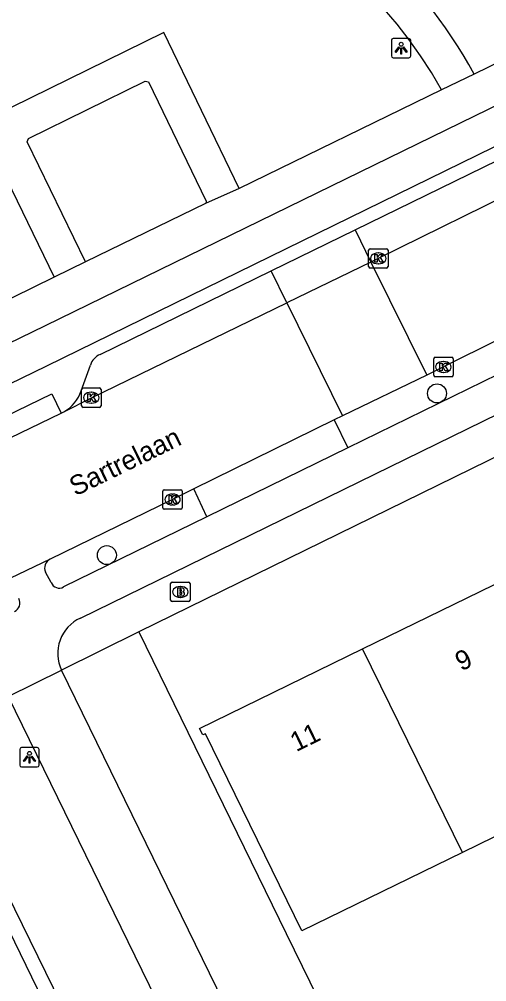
# Model space of a CAD drawing. Extents: x 160457 to 162082, y 388340 to 389736.
# Drawn here: x 160818.95 to 160843.03, y 388835.85 to 388885.46 of the extents above; entities that cross this region are included whole.
import ezdxf

# ---------------------------------------------------------------- set-up
doc = ezdxf.new("R2010")
doc.units = 0
for name, color, linetype in [('IMGEO_Berm_groen', 7, 'Continuous'), ('IMGEO_Boom', 7, 'Continuous'), ('IMGEO_Brandkraan', 7, 'Continuous'), ('IMGEO_Fietspad_gesloten', 7, 'Continuous'), ('IMGEO_Fietspad_open', 7, 'Continuous'), ('IMGEO_Kolk', 7, 'Continuous'), ('IMGEO_Lichtpunt', 7, 'Continuous'), ('IMGEO_Openbare_ruimte_label', 7, 'Continuous'), ('IMGEO_Pand', 7, 'Continuous'), ('IMGEO_Pand_nummerreeks', 7, 'Continuous'), ('IMGEO_Parkeervlak_open', 7, 'Continuous'), ('IMGEO_Rijbaan_lokaal_gesloten', 7, 'Continuous'), ('IMGEO_Rijbaan_lokaal_open', 7, 'Continuous'), ('IMGEO_Verkeerseiland_open', 7, 'Continuous'), ('IMGEO_Voetpad_open', 7, 'Continuous')]:
    doc.layers.add(name, color=color, linetype=linetype)

msp = doc.modelspace()

# ---------------------------------------------------------------- linework, layer by layer
at = {"layer": 'IMGEO_Berm_groen'}
for points in [[(160825.107, 388853.891), (160832.7, 388838.342), (160837.199, 388829.157)], [(160826.4, 388823.92), (160821.923, 388833.073), (160814.32, 388848.575)]]:
    msp.add_lwpolyline(points, dxfattribs=at)
at = {"layer": 'IMGEO_Boom'}
for centre in [(160840.468, 388866.179), (160823.466, 388857.844)]:
    msp.add_circle(centre, 0.489, dxfattribs=at)
at = {"layer": 'IMGEO_Brandkraan'}
for p, q in [((160826.75, 388855.52), (160826.75, 388856.372)), ((160826.825, 388856.446), (160827.677, 388856.446)), ((160827.238, 388856.226), (160827.263, 388856.226)), ((160827.751, 388856.372), (160827.751, 388855.52)), ((160827.677, 388855.446), (160826.825, 388855.446)), ((160827.261, 388855.666), (160827.236, 388855.666))]:
    msp.add_line(p, q, dxfattribs=at)
for points in [[(160826.75, 388855.52), (160826.75, 388856.372)], [(160826.825, 388856.446), (160827.677, 388856.446)], [(160827.751, 388856.372), (160827.751, 388855.52)], [(160827.098, 388856.146), (160827.098, 388855.746), (160827.311, 388855.746)], [(160827.329, 388856.146), (160827.098, 388856.146)], [(160827.277, 388856.065), (160827.223, 388856.065), (160827.223, 388855.989)], [(160827.223, 388855.989), (160827.276, 388855.989)], [(160827.285, 388855.913), (160827.223, 388855.913), (160827.223, 388855.832)], [(160827.223, 388855.832), (160827.285, 388855.832)], [(160827.677, 388855.446), (160826.825, 388855.446)]]:
    msp.add_lwpolyline(points, dxfattribs=at)
for centre, radius, start, end in [((160826.827, 388856.37), 0.0765, 91.552, 178.448), ((160826.827, 388856.37), 0.0765, 91.552, 178.448), ((160827.675, 388856.37), 0.0765, 1.552, 88.448), ((160827.675, 388856.37), 0.0765, 1.552, 88.448), ((160827.278, 388856.027), 0.0379, 267.8285, 90.9355), ((160827.286, 388855.872), 0.0404, 269.8759, 90.5077), ((160827.317, 388855.997), 0.251, 268.6676, 293.5347), ((160827.333, 388856.001), 0.145, 59.4692, 91.5367), ((160827.358, 388856.048), 0.0922, 285.5137, 58.1501), ((160827.363, 388855.856), 0.105, 301.3115, 78.989), ((160826.827, 388855.522), 0.0765, 181.552, 268.448), ((160826.827, 388855.522), 0.0765, 181.552, 268.448), ((160827.675, 388855.522), 0.0765, 271.552, 358.448), ((160827.675, 388855.522), 0.0765, 271.552, 358.448)]:
    msp.add_arc(centre, radius, start, end, dxfattribs=at)
for centre, major_axis, ratio, start_param, end_param in [((160827.237, 388855.946), (-0.387, 0.002), 0.722429, 4.712389, 7.853982), ((160827.262, 388855.946), (-0.39, 0.002), 0.717154, 1.570796, 4.712389)]:
    msp.add_ellipse(centre, major_axis=major_axis, ratio=ratio, start_param=start_param, end_param=end_param, dxfattribs=at)
at = {"layer": 'IMGEO_Fietspad_gesloten'}
for points in [[(160812.524, 388865.895), (160820.314, 388869.678), (160924.149, 388920.448), (160929.542, 388923.081)], [(160909.887, 388911.468), (160820.353, 388867.581), (160804.958, 388860.084), (160761.388, 388838.743), (160740.999, 388828.766), (160723.804, 388820.325)]]:
    msp.add_lwpolyline(points, dxfattribs=at)
at = {"layer": 'IMGEO_Fietspad_open'}
for points in [[(160822.105, 388854.6), (160868.356, 388877.242), (160931.655, 388908.25)], [(160844.374, 388867.53), (160835.881, 388863.365)], [(160835.881, 388863.365), (160828.618, 388859.824)], [(160828.618, 388859.824), (160821.23, 388856.204)], [(160820.601, 388856.424), (160820.3, 388856.966)]]:
    msp.add_lwpolyline(points, dxfattribs=at)
for centre, radius, start, end in [((160820.788, 388857.172), 0.529, 118.04, 202.8574), ((160821.008, 388856.579), 0.436, 200.8773, 300.567), ((160818.502, 388855.371), 0.485, 295.3905, 28.3574), ((160822.935, 388852.782), 1.999, 114.5332, 205.9112)]:
    msp.add_arc(centre, radius, start, end, dxfattribs=at)
at = {"layer": 'IMGEO_Kolk'}
for p, q in [((160837.019, 388873.637), (160837.871, 388873.637)), ((160836.944, 388872.711), (160836.944, 388873.563)), ((160837.432, 388873.417), (160837.457, 388873.417)), ((160837.945, 388873.563), (160837.945, 388872.711)), ((160837.871, 388872.637), (160837.019, 388872.637)), ((160837.455, 388872.857), (160837.43, 388872.857)), ((160840.296, 388867.114), (160840.296, 388867.966)), ((160840.371, 388868.04), (160841.223, 388868.04)), ((160840.784, 388867.82), (160840.809, 388867.82)), ((160841.297, 388867.966), (160841.297, 388867.114)), ((160840.807, 388867.26), (160840.782, 388867.26)), ((160841.223, 388867.04), (160840.371, 388867.04)), ((160822.165, 388865.531), (160822.165, 388866.383)), ((160822.24, 388866.457), (160823.092, 388866.457)), ((160822.653, 388866.237), (160822.678, 388866.237)), ((160823.166, 388866.383), (160823.166, 388865.531)), ((160822.676, 388865.677), (160822.651, 388865.677)), ((160823.092, 388865.457), (160822.24, 388865.457)), ((160826.422, 388861.21), (160827.274, 388861.21)), ((160826.347, 388860.284), (160826.347, 388861.136)), ((160826.835, 388860.99), (160826.86, 388860.99)), ((160827.348, 388861.136), (160827.348, 388860.284)), ((160827.274, 388860.21), (160826.422, 388860.21)), ((160826.858, 388860.43), (160826.833, 388860.43))]:
    msp.add_line(p, q, dxfattribs=at)
for points in [[(160837.019, 388873.637), (160837.871, 388873.637)], [(160836.944, 388872.711), (160836.944, 388873.563)], [(160837.265, 388873.337), (160837.388, 388873.337), (160837.388, 388873.186), (160837.518, 388873.337), (160837.682, 388873.337), (160837.536, 388873.186), (160837.689, 388872.937), (160837.537, 388872.937), (160837.452, 388873.101), (160837.388, 388873.034), (160837.388, 388872.937), (160837.265, 388872.937), (160837.265, 388873.337)], [(160837.945, 388873.563), (160837.945, 388872.711)], [(160837.871, 388872.637), (160837.019, 388872.637)], [(160840.296, 388867.114), (160840.296, 388867.966)], [(160840.371, 388868.04), (160841.223, 388868.04)], [(160840.617, 388867.74), (160840.74, 388867.74), (160840.74, 388867.589), (160840.87, 388867.74), (160841.034, 388867.74), (160840.888, 388867.589), (160841.041, 388867.34), (160840.889, 388867.34), (160840.804, 388867.504), (160840.74, 388867.437), (160840.74, 388867.34), (160840.617, 388867.34), (160840.617, 388867.74)], [(160841.297, 388867.966), (160841.297, 388867.114)], [(160841.223, 388867.04), (160840.371, 388867.04)], [(160822.165, 388865.531), (160822.165, 388866.383)], [(160822.24, 388866.457), (160823.092, 388866.457)], [(160822.486, 388866.157), (160822.609, 388866.157), (160822.609, 388866.006), (160822.739, 388866.157), (160822.903, 388866.157), (160822.757, 388866.006), (160822.91, 388865.757), (160822.758, 388865.757), (160822.673, 388865.921), (160822.609, 388865.854), (160822.609, 388865.757), (160822.486, 388865.757), (160822.486, 388866.157)], [(160823.166, 388866.383), (160823.166, 388865.531)], [(160823.092, 388865.457), (160822.24, 388865.457)], [(160826.422, 388861.21), (160827.274, 388861.21)], [(160826.347, 388860.284), (160826.347, 388861.136)], [(160826.668, 388860.91), (160826.791, 388860.91), (160826.791, 388860.759), (160826.921, 388860.91), (160827.085, 388860.91), (160826.939, 388860.759), (160827.092, 388860.51), (160826.94, 388860.51), (160826.855, 388860.674), (160826.791, 388860.607), (160826.791, 388860.51), (160826.668, 388860.51), (160826.668, 388860.91)], [(160827.348, 388861.136), (160827.348, 388860.284)], [(160827.274, 388860.21), (160826.422, 388860.21)]]:
    msp.add_lwpolyline(points, dxfattribs=at)
for centre, start, end in [((160837.021, 388873.561), 91.552, 178.448), ((160837.021, 388873.561), 91.552, 178.448), ((160837.869, 388873.561), 1.552, 88.448), ((160837.869, 388873.561), 1.552, 88.448), ((160837.021, 388872.713), 181.552, 268.448), ((160837.021, 388872.713), 181.552, 268.448), ((160837.869, 388872.713), 271.552, 358.448), ((160837.869, 388872.713), 271.552, 358.448), ((160840.373, 388867.964), 91.552, 178.448), ((160840.373, 388867.964), 91.552, 178.448), ((160841.221, 388867.964), 1.552, 88.448), ((160841.221, 388867.964), 1.552, 88.448), ((160840.373, 388867.116), 181.552, 268.448), ((160840.373, 388867.116), 181.552, 268.448), ((160841.221, 388867.116), 271.552, 358.448), ((160841.221, 388867.116), 271.552, 358.448), ((160822.242, 388866.381), 91.552, 178.448), ((160822.242, 388866.381), 91.552, 178.448), ((160823.09, 388866.381), 1.552, 88.448), ((160823.09, 388866.381), 1.552, 88.448), ((160822.242, 388865.533), 181.552, 268.448), ((160822.242, 388865.533), 181.552, 268.448), ((160823.09, 388865.533), 271.552, 358.448), ((160823.09, 388865.533), 271.552, 358.448), ((160826.424, 388861.134), 91.552, 178.448), ((160826.424, 388861.134), 91.552, 178.448), ((160827.272, 388861.134), 1.552, 88.448), ((160827.272, 388861.134), 1.552, 88.448), ((160826.424, 388860.286), 181.552, 268.448), ((160826.424, 388860.286), 181.552, 268.448), ((160827.272, 388860.286), 271.552, 358.448), ((160827.272, 388860.286), 271.552, 358.448)]:
    msp.add_arc(centre, 0.0765, start, end, dxfattribs=at)
for centre, major_axis, ratio, start_param, end_param in [((160837.431, 388873.137), (-0.387, 0.002), 0.722429, 4.712389, 7.853982), ((160837.456, 388873.137), (-0.39, 0.002), 0.717154, 1.570796, 4.712389), ((160840.783, 388867.54), (-0.387, 0.002), 0.722429, 4.712389, 7.853982), ((160840.808, 388867.54), (-0.39, 0.002), 0.717154, 1.570796, 4.712389), ((160822.652, 388865.957), (-0.387, 0.002), 0.722429, 4.712389, 7.853982), ((160822.677, 388865.957), (-0.39, 0.002), 0.717154, 1.570796, 4.712389), ((160826.834, 388860.71), (-0.387, 0.002), 0.722429, 4.712389, 7.853982), ((160826.859, 388860.71), (-0.39, 0.002), 0.717154, 1.570796, 4.712389)]:
    msp.add_ellipse(centre, major_axis=major_axis, ratio=ratio, start_param=start_param, end_param=end_param, dxfattribs=at)
at = {"layer": 'IMGEO_Lichtpunt'}
for p, q in [((160838.122, 388884.377), (160838.122, 388883.57)), ((160838.122, 388884.377), (160838.122, 388883.57)), ((160839.024, 388884.472), (160838.216, 388884.472)), ((160839.024, 388884.472), (160838.216, 388884.472)), ((160839.118, 388883.57), (160839.118, 388884.377)), ((160839.118, 388883.57), (160839.118, 388884.377)), ((160838.216, 388883.476), (160839.024, 388883.476)), ((160838.216, 388883.476), (160839.024, 388883.476)), ((160818.98, 388847.826), (160818.98, 388847.019)), ((160818.98, 388847.826), (160818.98, 388847.019)), ((160819.882, 388847.921), (160819.074, 388847.921)), ((160819.882, 388847.921), (160819.074, 388847.921)), ((160819.976, 388847.019), (160819.976, 388847.826)), ((160819.976, 388847.019), (160819.976, 388847.826)), ((160819.074, 388846.925), (160819.882, 388846.925)), ((160819.074, 388846.925), (160819.882, 388846.925))]:
    msp.add_line(p, q, dxfattribs=at)
for points in [[(160838.496, 388884.041), (160838.535, 388884.013), (160838.347, 388883.751), (160838.309, 388883.778), (160838.496, 388884.041)], [(160838.708, 388884.013), (160838.746, 388884.04), (160838.933, 388883.778), (160838.894, 388883.75), (160838.708, 388884.013)], [(160838.598, 388883.993), (160838.645, 388883.993), (160838.645, 388883.671), (160838.598, 388883.671), (160838.598, 388883.993)], [(160819.354, 388847.49), (160819.393, 388847.462), (160819.205, 388847.2), (160819.167, 388847.227), (160819.354, 388847.49)], [(160819.456, 388847.442), (160819.503, 388847.442), (160819.503, 388847.12), (160819.456, 388847.12), (160819.456, 388847.442)], [(160819.566, 388847.462), (160819.604, 388847.489), (160819.791, 388847.227), (160819.752, 388847.199), (160819.566, 388847.462)]]:
    msp.add_lwpolyline(points, dxfattribs=at)
for centre in [(160838.621, 388884.175), (160819.479, 388847.624)]:
    msp.add_circle(centre, 0.0994, dxfattribs=at)
for centre, start, end in [((160838.216, 388884.377), 90, 180), ((160838.216, 388884.377), 90, 180), ((160839.024, 388884.377), 0, 90), ((160839.024, 388884.377), 0, 90), ((160838.216, 388883.57), 180, 270), ((160838.216, 388883.57), 180, 270), ((160839.024, 388883.57), 270, 0), ((160839.024, 388883.57), 270, 360), ((160819.074, 388847.826), 90, 180), ((160819.074, 388847.826), 90, 180), ((160819.882, 388847.826), 0, 90), ((160819.882, 388847.826), 0, 90), ((160819.074, 388847.019), 180, 270), ((160819.074, 388847.019), 180, 270), ((160819.882, 388847.019), 270, 0), ((160819.882, 388847.019), 270, 360)]:
    msp.add_arc(centre, 0.0946, start, end, dxfattribs=at)
at = {"layer": 'IMGEO_Pand'}
for points in [[(160836.639, 388853.011), (160844.731, 388856.965)], [(160841.784, 388842.524), (160833.503, 388838.478), (160828.537, 388848.637), (160828.406, 388848.582), (160828.242, 388848.909), (160836.639, 388853.011)], [(160841.784, 388842.524), (160836.639, 388853.011)], [(160849.877, 388846.477), (160841.784, 388842.524)], [(160807.926, 388838.972), (160816.305, 388843.064), (160816.478, 388842.742), (160816.37, 388842.689), (160821.325, 388832.529), (160813.027, 388828.476)]]:
    msp.add_lwpolyline(points, dxfattribs=at)
at = {"layer": 'IMGEO_Parkeervlak_open'}
for points in [[(160836.249, 388874.605), (160866.313, 388889.309)], [(160831.931, 388872.494), (160836.249, 388874.605)], [(160836.249, 388874.605), (160837.066, 388872.948)], [(160823.121, 388868.185), (160831.931, 388872.494)], [(160832.74, 388870.849), (160831.931, 388872.494)], [(160822.145, 388866.315), (160822.616, 388867.637)]]:
    msp.add_lwpolyline(points, dxfattribs=at)
for centre, radius, start, end in [((160823.452, 388867.374), 0.876, 112.1711, 162.5057), ((160820.296, 388866.929), 1.948, 299.5152, 341.618)]:
    msp.add_arc(centre, radius, start, end, dxfattribs=at)
at = {"layer": 'IMGEO_Rijbaan_lokaal_gesloten'}
for points in [[(160869.671, 388888.959), (160868.404, 388888.341), (160852.789, 388880.69), (160837.429, 388873.127), (160837.066, 388872.948)], [(160821.256, 388865.234), (160822.666, 388865.956), (160832.74, 388870.849)], [(160843.672, 388868.965), (160840.796, 388867.541), (160839.938, 388867.126)], [(160809.001, 388859.296), (160821.118, 388865.164)], [(160821.118, 388865.164), (160821.256, 388865.234)], [(160835.171, 388864.819), (160827.943, 388861.264)], [(160835.602, 388865.027), (160835.171, 388864.819)], [(160827.943, 388861.264), (160826.848, 388860.711), (160820.539, 388857.639)], [(160820.539, 388857.639), (160818.08, 388856.442)]]:
    msp.add_lwpolyline(points, dxfattribs=at)
at = {"layer": 'IMGEO_Rijbaan_lokaal_open'}
for points in [[(160837.066, 388872.948), (160832.74, 388870.849)], [(160837.066, 388872.948), (160839.938, 388867.126)], [(160832.74, 388870.849), (160835.602, 388865.027)], [(160839.938, 388867.126), (160835.602, 388865.027)], [(160818.384, 388850.563), (160821.137, 388851.908)], [(160832.392, 388828.839), (160821.137, 388851.908)], [(160818.384, 388850.563), (160829.631, 388827.513)]]:
    msp.add_lwpolyline(points, dxfattribs=at)
at = {"layer": 'IMGEO_Verkeerseiland_open'}
for points in [[(160809.001, 388859.296), (160808.522, 388860.286), (160820.639, 388866.154), (160821.118, 388865.164)], [(160835.171, 388864.819), (160835.881, 388863.365)], [(160828.618, 388859.824), (160827.943, 388861.264)]]:
    msp.add_lwpolyline(points, dxfattribs=at)
at = {"layer": 'IMGEO_Voetpad_open'}
for points in [[(160868.202, 388895.257), (160842.385, 388882.64)], [(160830.287, 388876.733), (160826.407, 388884.773), (160818.534, 388880.906), (160813.316, 388891.537)], [(160842.385, 388882.64), (160840.695, 388881.816)], [(160822.373, 388872.952), (160819.368, 388879.142), (160819.423, 388879.311), (160825.438, 388882.278), (160825.609, 388882.23), (160828.571, 388876.125)], [(160840.695, 388881.816), (160830.287, 388876.733)], [(160876.34, 388878.995), (160869.603, 388875.706), (160825.107, 388853.891)], [(160814.423, 388869.063), (160811.392, 388875.22), (160811.451, 388875.37), (160817.608, 388878.42), (160817.735, 388878.364), (160820.748, 388872.176)], [(160830.287, 388876.733), (160828.55, 388875.97)], [(160828.55, 388875.97), (160822.373, 388872.952)], [(160822.373, 388872.952), (160820.748, 388872.176)], [(160820.748, 388872.176), (160814.423, 388869.063)], [(160825.107, 388853.891), (160821.137, 388851.908)]]:
    msp.add_lwpolyline(points, dxfattribs=at)
for centre, radius, start, end in [((160821.631, 388871.366), 23.619, 28.511, 112.6638), ((160821.579, 388871.393), 21.773, 28.6014, 112.3034), ((160828.484, 388876.058), 0.11, 306.7661, 37.8025)]:
    msp.add_arc(centre, radius, start, end, dxfattribs=at)

# ---------------------------------------------------------------- texts
at = {"layer": 'IMGEO_Openbare_ruimte_label'}
msp.add_text('Sartrelaan', height=1, rotation=26.0272, dxfattribs=at).set_placement((160821.846, 388860.863))
at = {"layer": 'IMGEO_Pand_nummerreeks'}
for s, p in [('9', (160841.716, 388851.842)), ('11', (160833.218, 388847.689))]:
    msp.add_text(s, height=1, rotation=26.0388, dxfattribs=at).set_placement(p)

doc.saveas('drawing.dxf')
